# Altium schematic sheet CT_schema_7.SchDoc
size 366 x 245 mm
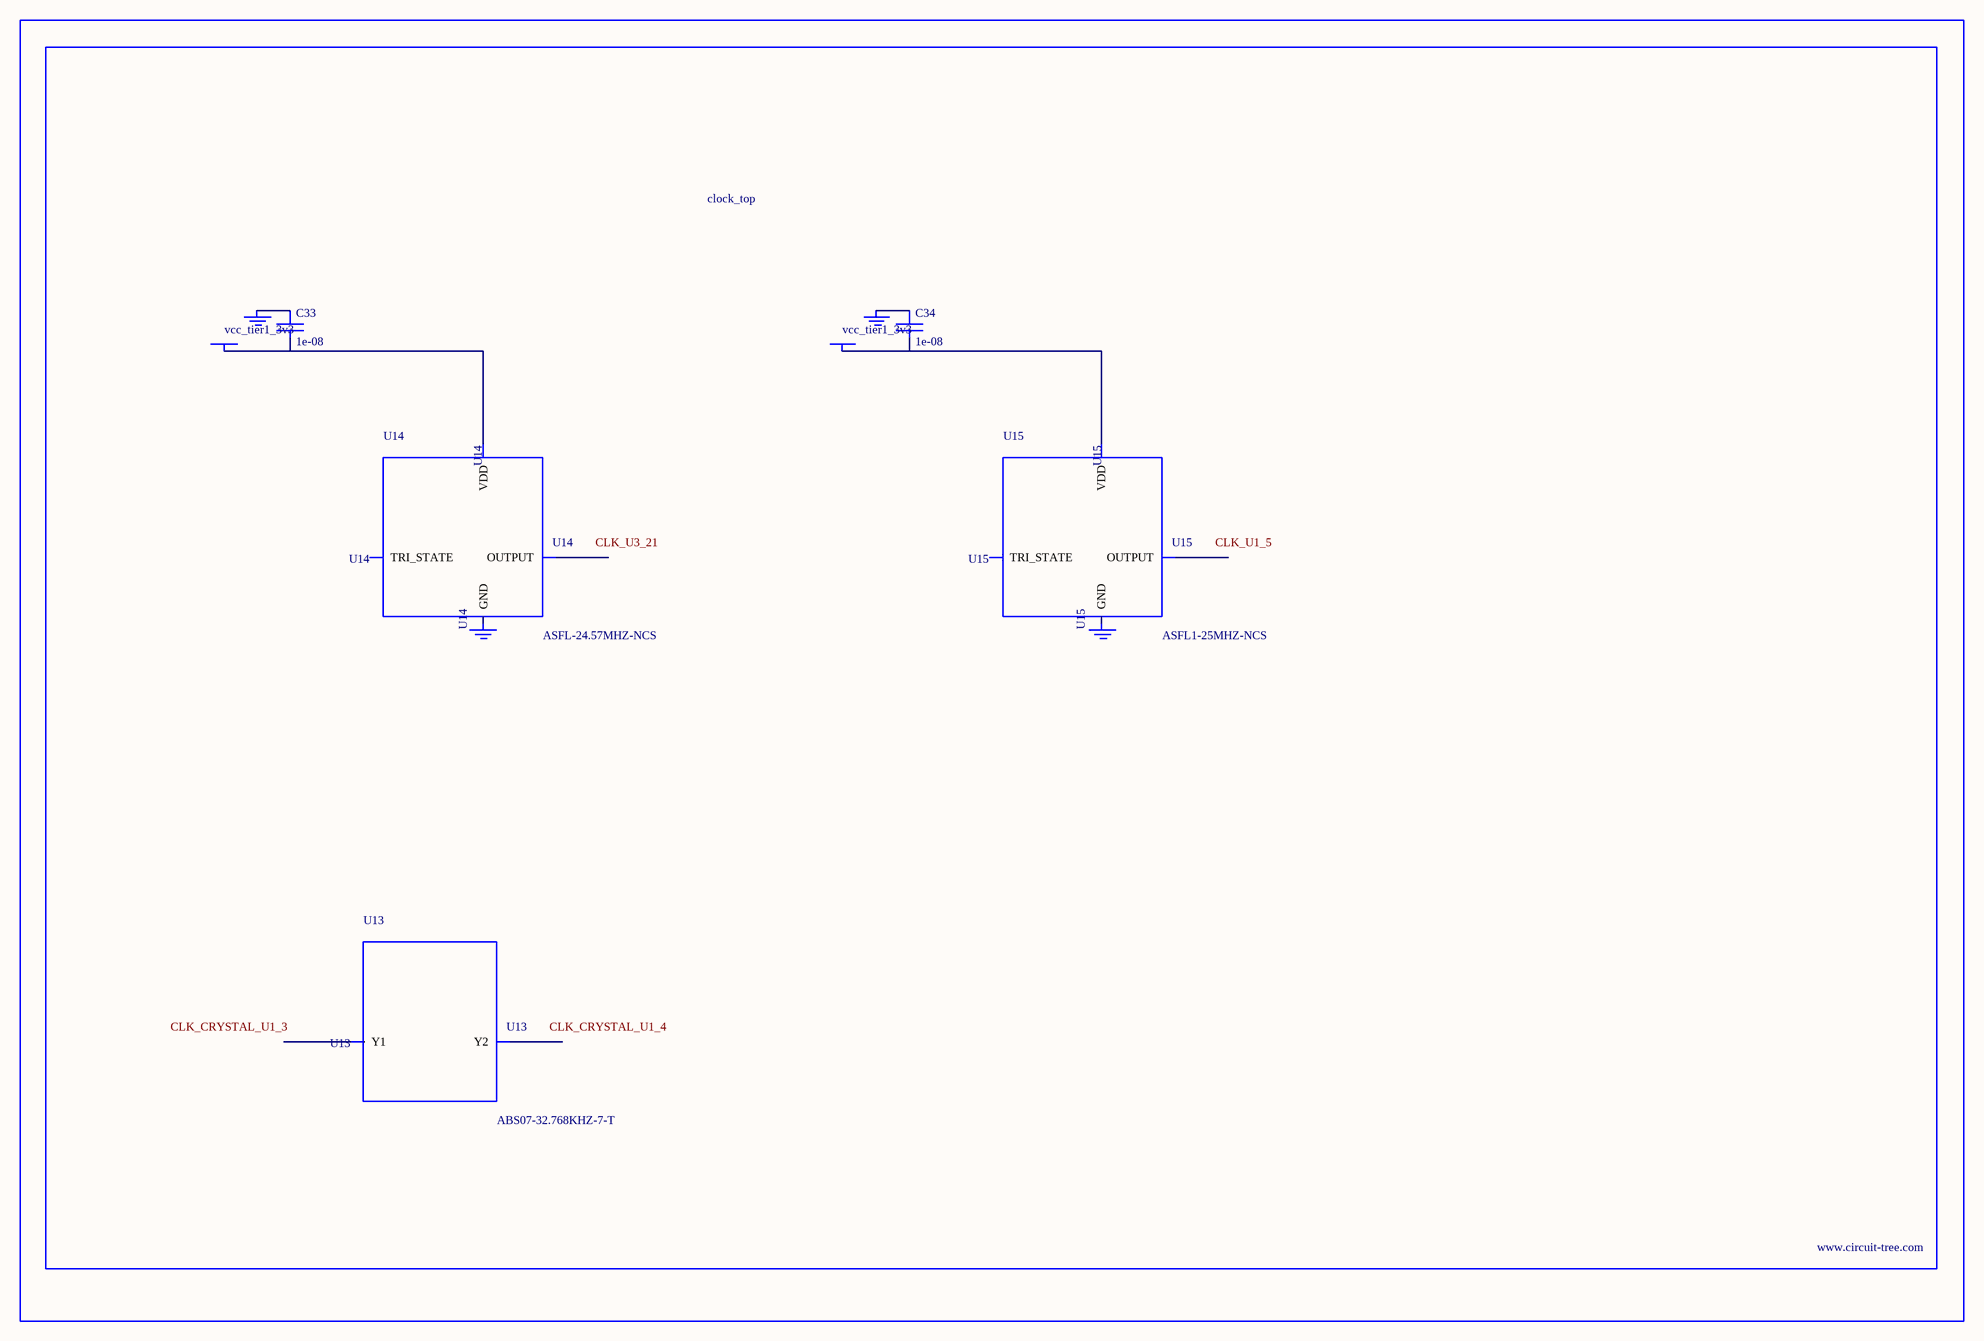
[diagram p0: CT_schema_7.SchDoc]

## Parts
BORDER6  (no value)
C33  1e-08  [C0402]
C34  1e-08  [C0402]
GND_INSTANCE_6_0  (no value)
GND_INSTANCE_6_1  (no value)
GND_INSTANCE_6_2  (no value)
GND_INSTANCE_6_3  (no value)
POWER_INSTANCE_6_0  vcc_tier1_3v3
POWER_INSTANCE_6_1  vcc_tier1_3v3
U13  ABS07-32.768KHZ-7-T  [ABS07-32.768KHZ-7-T]
U14  ASFL-24.57MHZ-NCS  [ASFL1]
U15  ASFL1-25MHZ-NCS  [ASFL1]

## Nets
NetC33_1: C33.1 GND_INSTANCE_6_0.0(GND)
NetC33_2: C33.2 POWER_INSTANCE_6_0.0(PWR) U14.4(VDD)
NetC34_1: C34.1 GND_INSTANCE_6_2.0(GND)
NetC34_2: C34.2 POWER_INSTANCE_6_1.0(PWR) U15.4(VDD)

Not connected (* = marked no-connect by the designer): GND_INSTANCE_6_1 0(GND); GND_INSTANCE_6_3 0(GND); U13 1(Y1) 2(Y2); U14 1(TRI_STATE) 2(GND) 3(OUTPUT); U15 1(TRI_STATE) 2(GND) 3(OUTPUT)

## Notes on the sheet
- Labels drawn without touching a wire or pin: CLK_CRYSTAL_U1_3, CLK_CRYSTAL_U1_4, CLK_U1_5, CLK_U3_21

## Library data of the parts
BORDER6 = BORDER_PAGE6
C33 C34 = C0402C103K3RAC
GND_INSTANCE_6_0-GND_INSTANCE_6_3 = GND
POWER_INSTANCE_6_0 POWER_INSTANCE_6_1 = PWR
